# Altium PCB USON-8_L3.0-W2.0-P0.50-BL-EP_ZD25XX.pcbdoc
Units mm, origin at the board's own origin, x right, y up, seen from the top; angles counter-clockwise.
Board outline 14.95 x 16.4 mm, 2 copper layers (Top Layer, Bottom Layer), stack 0 mm thick; 1 components, 0 nets, 9 pads, 0 vias.
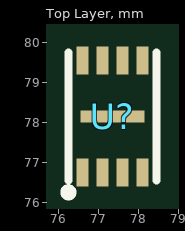
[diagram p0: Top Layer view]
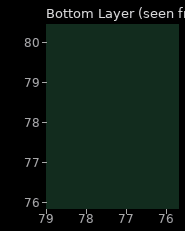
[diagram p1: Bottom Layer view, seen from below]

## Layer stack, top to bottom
Top Layer: signal copper (thickness not stored)
Bottom Layer: signal copper (thickness not stored)

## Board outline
84.801,69.85 69.85,69.85 69.85,86.249 84.801,86.249

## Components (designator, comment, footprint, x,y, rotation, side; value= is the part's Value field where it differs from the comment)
U? "" USON-8_L3.0-W2.0-P0.50-BL-EP_ZD25XX 77.351,78.151 r0 top

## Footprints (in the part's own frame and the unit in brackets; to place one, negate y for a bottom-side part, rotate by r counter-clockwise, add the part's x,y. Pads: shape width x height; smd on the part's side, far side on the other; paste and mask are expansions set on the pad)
USON-8_L3.0-W2.0-P0.50-BL-EP_ZD25XX [mm]
  rect 0.3x0.7 smd: 1(-0.75,-1.398) 2(-0.25,-1.398) 3(0.25,-1.398) 4(0.75,-1.398) 5(0.75,1.398) 6(0.25,1.398) 7(-0.25,1.398) 8(-0.75,1.398)
  rect 1.6x0.3 smd: 9(0,0)
  silkscreen extent -1.15,-1.95 1.1,1.6

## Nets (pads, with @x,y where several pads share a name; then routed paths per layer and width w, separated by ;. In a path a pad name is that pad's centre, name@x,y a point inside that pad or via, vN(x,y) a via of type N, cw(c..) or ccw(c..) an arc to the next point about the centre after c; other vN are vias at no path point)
pads on no net: U?.1 U?.2 U?.3 U?.4 U?.5 U?.6 U?.7 U?.8 U?.9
